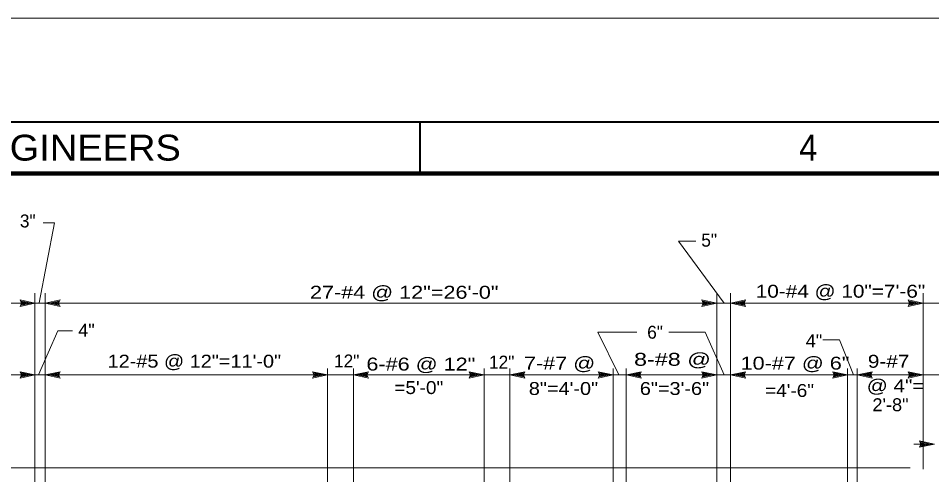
# Model space of a CAD drawing. Extents: x -22.3 to 19.7, y -11.8 to 18.2.
# Drawn here: x -17.19 to -8.36, y 13.75 to 18.16 of the extents above; entities that cross this region are included whole.
import ezdxf
from ezdxf.enums import TextEntityAlignment as Align

# ---------------------------------------------------------------- set-up
doc = ezdxf.new("R2010")
doc.units = 0
doc.header["$LTSCALE"] = 0.05
doc.layers.add('1', color=7, linetype='Continuous', lineweight=13)

msp = doc.modelspace()

# ---------------------------------------------------------------- linework, layer by layer
at = {"layer": '1', "lineweight": 40}
msp.add_line((-13.30942, 17.16031), (-13.30942, 16.66031), dxfattribs=at)
at = {"layer": '1'}
for p, q in [((-10.36542, 15.40731), (-10.80942, 16.00631)), ((-10.80942, 16.00631), (-10.63942, 16.00631)), ((-17.03142, 9.51631), (-17.03142, 15.50531)), ((-16.93242, 9.51631), (-16.93242, 15.50531)), ((-10.43842, 12.78231), (-10.43842, 15.50531)), ((-10.30342, 12.84831), (-10.30342, 15.50531)), ((-8.44242, 13.80331), (-8.44242, 15.50531)), ((-17.03142, 15.40731), (-17.17542, 15.43831)), ((-17.03142, 15.40731), (-17.17542, 15.37631)), ((-17.06842, 15.40731), (-17.16242, 15.42731)), ((-17.15342, 15.40731), (-17.16242, 15.42731)), ((-17.06842, 15.40731), (-17.16242, 15.38731)), ((-17.16242, 15.38731), (-17.15342, 15.40731)), ((-17.10442, 15.40731), (-17.14942, 15.41631)), ((-17.14542, 15.40731), (-17.14942, 15.41631)), ((-17.10442, 15.40731), (-17.14942, 15.39731)), ((-17.14942, 15.39731), (-17.14542, 15.40731)), ((-16.93242, 15.40731), (-16.78842, 15.43831)), ((-16.93242, 15.40731), (-16.78842, 15.37631)), ((-16.89542, 15.40731), (-16.80142, 15.42731)), ((-16.89542, 15.40731), (-16.80142, 15.38731)), ((-16.85942, 15.40731), (-16.81442, 15.41731)), ((-16.85942, 15.40731), (-16.81442, 15.39831)), ((-16.81442, 15.41731), (-16.81842, 15.40731)), ((-16.81842, 15.40731), (-16.81442, 15.39831)), ((-16.80142, 15.42731), (-16.81042, 15.40731)), ((-16.81042, 15.40731), (-16.80142, 15.38731)), ((-10.43842, 15.40731), (-10.58242, 15.43831)), ((-10.43842, 15.40731), (-10.58242, 15.37631)), ((-10.47542, 15.40731), (-10.56942, 15.42731)), ((-10.56042, 15.40731), (-10.56942, 15.42731)), ((-10.47542, 15.40731), (-10.56942, 15.38731)), ((-10.56942, 15.38731), (-10.56042, 15.40731)), ((-10.51142, 15.40731), (-10.55642, 15.41631)), ((-10.55242, 15.40731), (-10.55642, 15.41631)), ((-10.51142, 15.40731), (-10.55642, 15.39731)), ((-10.55642, 15.39731), (-10.55242, 15.40731)), ((-10.30242, 15.40731), (-10.15842, 15.43831)), ((-10.30242, 15.40731), (-10.15842, 15.37631)), ((-10.26542, 15.40731), (-10.17142, 15.42731)), ((-10.26542, 15.40731), (-10.17142, 15.38731)), ((-10.22942, 15.40731), (-10.18442, 15.41731)), ((-10.22942, 15.40731), (-10.18442, 15.39831)), ((-10.18442, 15.41731), (-10.18842, 15.40731)), ((-10.18842, 15.40731), (-10.18442, 15.39831)), ((-10.17142, 15.42731), (-10.18042, 15.40731)), ((-10.18042, 15.40731), (-10.17142, 15.38731)), ((-8.44242, 15.40731), (-8.58642, 15.43831)), ((-8.44242, 15.40731), (-8.58642, 15.37631)), ((-8.47942, 15.40731), (-8.57342, 15.42731)), ((-8.56442, 15.40731), (-8.57342, 15.42731)), ((-8.47942, 15.40731), (-8.57342, 15.38731)), ((-8.57342, 15.38731), (-8.56442, 15.40731)), ((-8.51542, 15.40731), (-8.56042, 15.41631)), ((-8.55642, 15.40731), (-8.56042, 15.41631)), ((-8.51542, 15.40731), (-8.56042, 15.39731)), ((-8.56042, 15.39731), (-8.55642, 15.40731)), ((-16.81042, 15.13931), (-16.99742, 14.71431)), ((-16.81042, 15.13931), (-16.66942, 15.13931)), ((-11.38342, 14.71431), (-11.58742, 15.12631)), ((-11.58742, 15.12631), (-11.21142, 15.12631)), ((-10.90242, 15.12631), (-10.55042, 15.12631)), ((-10.55042, 15.12631), (-10.36542, 14.71431)), ((-14.20242, 10.90131), (-14.20242, 14.77631)), ((-13.95142, 11.04731), (-13.95142, 14.77631)), ((-12.68842, 11.68931), (-12.68842, 14.77631)), ((-12.43842, 11.79131), (-12.43842, 14.77631)), ((-11.43942, 12.29431), (-11.43942, 14.77631)), ((-11.31242, 10.81431), (-11.31242, 14.77631)), ((-9.17242, 13.43131), (-9.17242, 14.77631)), ((-9.08142, 10.74131), (-9.08142, 14.77631)), ((-17.03142, 14.71431), (-17.17542, 14.74531)), ((-17.03142, 14.71431), (-17.17542, 14.68331)), ((-17.06842, 14.71431), (-17.16242, 14.73431)), ((-17.15342, 14.71431), (-17.16242, 14.73431)), ((-17.06842, 14.71431), (-17.16242, 14.69431)), ((-17.16242, 14.69431), (-17.15342, 14.71431)), ((-17.10442, 14.71431), (-17.14942, 14.72331)), ((-17.14542, 14.71431), (-17.14942, 14.72331)), ((-17.10442, 14.71431), (-17.14942, 14.70431)), ((-17.14942, 14.70431), (-17.14542, 14.71431)), ((-16.93242, 14.71431), (-16.78842, 14.74531)), ((-16.93242, 14.71431), (-16.78842, 14.68331)), ((-16.89542, 14.71431), (-16.80142, 14.73431)), ((-16.89542, 14.71431), (-16.80142, 14.69431)), ((-16.85942, 14.71431), (-16.81442, 14.72431)), ((-16.85942, 14.71431), (-16.81442, 14.70531)), ((-16.81442, 14.72431), (-16.81842, 14.71431)), ((-16.81842, 14.71431), (-16.81442, 14.70531)), ((-16.80142, 14.73431), (-16.81042, 14.71431)), ((-16.81042, 14.71431), (-16.80142, 14.69431)), ((-14.20242, 14.71431), (-14.34642, 14.74531)), ((-14.20242, 14.71431), (-14.34642, 14.68331)), ((-14.23942, 14.71431), (-14.33342, 14.73431)), ((-14.32442, 14.71431), (-14.33342, 14.73431)), ((-14.23942, 14.71431), (-14.33342, 14.69431)), ((-14.33342, 14.69431), (-14.32442, 14.71431)), ((-14.27542, 14.71431), (-14.32042, 14.72331)), ((-14.31642, 14.71431), (-14.32042, 14.72331)), ((-14.27542, 14.71431), (-14.32042, 14.70431)), ((-14.32042, 14.70431), (-14.31642, 14.71431)), ((-13.95142, 14.71431), (-13.80742, 14.74531)), ((-13.95142, 14.71431), (-13.80742, 14.68331)), ((-13.91442, 14.71431), (-13.82042, 14.73431)), ((-13.91442, 14.71431), (-13.82042, 14.69431)), ((-13.87842, 14.71431), (-13.83342, 14.72431)), ((-13.87842, 14.71431), (-13.83342, 14.70531)), ((-13.83342, 14.72431), (-13.83742, 14.71431)), ((-13.83742, 14.71431), (-13.83342, 14.70531)), ((-13.82042, 14.73431), (-13.82942, 14.71431)), ((-13.82942, 14.71431), (-13.82042, 14.69431)), ((-12.68842, 14.71431), (-12.83242, 14.74531)), ((-12.68842, 14.71431), (-12.83242, 14.68331)), ((-12.72542, 14.71431), (-12.81942, 14.73431)), ((-12.81042, 14.71431), (-12.81942, 14.73431)), ((-12.72542, 14.71431), (-12.81942, 14.69431)), ((-12.81942, 14.69431), (-12.81042, 14.71431)), ((-12.76142, 14.71431), (-12.80642, 14.72331)), ((-12.80242, 14.71431), (-12.80642, 14.72331)), ((-12.76142, 14.71431), (-12.80642, 14.70431)), ((-12.80642, 14.70431), (-12.80242, 14.71431)), ((-12.43842, 14.71431), (-12.29442, 14.74531)), ((-12.43842, 14.71431), (-12.29442, 14.68331)), ((-12.40142, 14.71431), (-12.30742, 14.73431)), ((-12.40142, 14.71431), (-12.30742, 14.69431)), ((-12.36542, 14.71431), (-12.32042, 14.72431)), ((-12.36542, 14.71431), (-12.32042, 14.70531)), ((-12.32042, 14.72431), (-12.32442, 14.71431)), ((-12.32442, 14.71431), (-12.32042, 14.70531)), ((-12.30742, 14.73431), (-12.31642, 14.71431)), ((-12.31642, 14.71431), (-12.30742, 14.69431)), ((-11.43942, 14.71431), (-11.58342, 14.74531)), ((-11.43942, 14.71431), (-11.58342, 14.68331)), ((-11.47642, 14.71431), (-11.57042, 14.73431)), ((-11.56142, 14.71431), (-11.57042, 14.73431)), ((-11.47642, 14.71431), (-11.57042, 14.69431)), ((-11.57042, 14.69431), (-11.56142, 14.71431)), ((-11.51242, 14.71431), (-11.55742, 14.72331)), ((-11.55342, 14.71431), (-11.55742, 14.72331)), ((-11.51242, 14.71431), (-11.55742, 14.70431)), ((-11.55742, 14.70431), (-11.55342, 14.71431)), ((-11.31142, 14.71431), (-11.16742, 14.74531)), ((-11.31142, 14.71431), (-11.16742, 14.68331)), ((-11.27442, 14.71431), (-11.18042, 14.73431)), ((-11.27442, 14.71431), (-11.18042, 14.69431)), ((-11.23842, 14.71431), (-11.19342, 14.72431)), ((-11.23842, 14.71431), (-11.19342, 14.70531)), ((-11.19342, 14.72431), (-11.19742, 14.71431)), ((-11.19742, 14.71431), (-11.19342, 14.70531)), ((-11.18042, 14.73431), (-11.18942, 14.71431)), ((-11.18942, 14.71431), (-11.18042, 14.69431)), ((-10.43842, 14.71431), (-10.58242, 14.74531)), ((-10.43842, 14.71431), (-10.58242, 14.68331)), ((-10.47542, 14.71431), (-10.56942, 14.73431)), ((-10.56042, 14.71431), (-10.56942, 14.73431)), ((-10.47542, 14.71431), (-10.56942, 14.69431)), ((-10.56942, 14.69431), (-10.56042, 14.71431)), ((-10.51142, 14.71431), (-10.55642, 14.72331)), ((-10.55242, 14.71431), (-10.55642, 14.72331)), ((-10.51142, 14.71431), (-10.55642, 14.70431)), ((-10.55642, 14.70431), (-10.55242, 14.71431)), ((-10.30342, 14.71431), (-10.15942, 14.74531)), ((-10.30342, 14.71431), (-10.15942, 14.68331)), ((-10.26642, 14.71431), (-10.17242, 14.73431)), ((-10.26642, 14.71431), (-10.17242, 14.69431)), ((-10.23042, 14.71431), (-10.18542, 14.72431)), ((-10.23042, 14.71431), (-10.18542, 14.70531)), ((-10.18542, 14.72431), (-10.18942, 14.71431)), ((-10.18942, 14.71431), (-10.18542, 14.70531)), ((-10.17242, 14.73431), (-10.18142, 14.71431)), ((-10.18142, 14.71431), (-10.17242, 14.69431)), ((-9.17242, 14.71431), (-9.31642, 14.74531)), ((-9.17242, 14.71431), (-9.31642, 14.68331)), ((-9.20942, 14.71431), (-9.30342, 14.73431)), ((-9.29442, 14.71431), (-9.30342, 14.73431)), ((-9.20942, 14.71431), (-9.30342, 14.69431)), ((-9.30342, 14.69431), (-9.29442, 14.71431)), ((-9.24542, 14.71431), (-9.29042, 14.72331)), ((-9.28642, 14.71431), (-9.29042, 14.72331)), ((-9.24542, 14.71431), (-9.29042, 14.70431)), ((-9.29042, 14.70431), (-9.28642, 14.71431)), ((-9.07942, 14.71431), (-8.93542, 14.74531)), ((-9.07942, 14.71431), (-8.93542, 14.68331)), ((-9.04242, 14.71431), (-8.94842, 14.73431)), ((-9.04242, 14.71431), (-8.94842, 14.69431)), ((-9.00642, 14.71431), (-8.96142, 14.72431)), ((-9.00642, 14.71431), (-8.96142, 14.70531)), ((-8.96142, 14.72431), (-8.96542, 14.71431)), ((-8.96542, 14.71431), (-8.96142, 14.70531)), ((-8.94842, 14.73431), (-8.95742, 14.71431)), ((-8.95742, 14.71431), (-8.94842, 14.69431)), ((-8.44242, 14.71431), (-8.58642, 14.74531)), ((-8.44242, 14.71431), (-8.58642, 14.68331)), ((-8.47942, 14.71431), (-8.57342, 14.73431)), ((-8.56442, 14.71431), (-8.57342, 14.73431)), ((-8.47942, 14.71431), (-8.57342, 14.69431)), ((-8.57342, 14.69431), (-8.56442, 14.71431)), ((-8.51542, 14.71431), (-8.56042, 14.72331)), ((-8.55642, 14.71431), (-8.56042, 14.72331)), ((-8.51542, 14.71431), (-8.56042, 14.70431)), ((-8.56042, 14.70431), (-8.55642, 14.71431)), ((-8.53242, 14.04631), (-8.33342, 14.04631)), ((-8.33342, 14.04631), (-8.47742, 14.07731)), ((-8.33342, 14.04631), (-8.47742, 14.01531)), ((-8.37042, 14.04631), (-8.46442, 14.06631)), ((-8.45542, 14.04631), (-8.46442, 14.06631)), ((-8.37042, 14.04631), (-8.46442, 14.02631)), ((-8.46442, 14.02631), (-8.45542, 14.04631)), ((-8.40642, 14.04631), (-8.45142, 14.05531)), ((-8.44742, 14.04631), (-8.45142, 14.05531)), ((-8.40642, 14.04631), (-8.45142, 14.03631)), ((-8.45142, 14.03631), (-8.44742, 14.04631)), ((-8.56742, 13.81631), (-19.00142, 13.81631))]:
    msp.add_line(p, q, dxfattribs=at)
for points in [[(-22.30942, 18.16031), (19.69058, 18.16031), (19.69058, -11.83969)], [(-16.95342, 16.18331), (-16.84342, 16.18331), (-16.99042, 15.41031)], [(-18.06742, 15.40731), (-17.03142, 15.40731), (-16.93242, 15.40731), (-10.43842, 15.40731), (-10.30242, 15.40731), (-8.44242, 15.40731), (-8.32942, 15.40731), (-7.44542, 15.40731)], [(-17.17542, 15.37631), (-17.16142, 15.40731), (-17.17542, 15.43831)], [(-16.78842, 15.43831), (-16.80242, 15.40731), (-16.78842, 15.37631)], [(-10.58242, 15.37631), (-10.56842, 15.40731), (-10.58242, 15.43831)], [(-10.15842, 15.43831), (-10.17242, 15.40731), (-10.15842, 15.37631)], [(-8.58642, 15.37631), (-8.57242, 15.40731), (-8.58642, 15.43831)], [(-9.11542, 14.71431), (-9.25242, 15.05231), (-9.41242, 15.05231)], [(-18.10442, 14.71431), (-17.03142, 14.71431), (-16.93242, 14.71431), (-14.20242, 14.71431), (-13.95142, 14.71431), (-12.68842, 14.71431), (-12.43842, 14.71431), (-11.43942, 14.71431), (-11.31142, 14.71431), (-10.43842, 14.71431), (-10.30342, 14.71431), (-9.17242, 14.71431), (-9.07942, 14.71431), (-8.44242, 14.71431), (-8.33342, 14.71431), (-7.78542, 14.71431)], [(-17.17542, 14.68331), (-17.16142, 14.71431), (-17.17542, 14.74531)], [(-16.78842, 14.74531), (-16.80242, 14.71431), (-16.78842, 14.68331)], [(-14.34642, 14.68331), (-14.33242, 14.71431), (-14.34642, 14.74531)], [(-13.80742, 14.74531), (-13.82142, 14.71431), (-13.80742, 14.68331)], [(-12.83242, 14.68331), (-12.81842, 14.71431), (-12.83242, 14.74531)], [(-12.29442, 14.74531), (-12.30842, 14.71431), (-12.29442, 14.68331)], [(-11.58342, 14.68331), (-11.56942, 14.71431), (-11.58342, 14.74531)], [(-11.16742, 14.74531), (-11.18142, 14.71431), (-11.16742, 14.68331)], [(-10.58242, 14.68331), (-10.56842, 14.71431), (-10.58242, 14.74531)], [(-10.15942, 14.74531), (-10.17342, 14.71431), (-10.15942, 14.68331)], [(-9.31642, 14.68331), (-9.30242, 14.71431), (-9.31642, 14.74531)], [(-8.93542, 14.74531), (-8.94942, 14.71431), (-8.93542, 14.68331)], [(-8.58642, 14.68331), (-8.57242, 14.71431), (-8.58642, 14.74531)], [(-8.47742, 14.01531), (-8.46342, 14.04631), (-8.47742, 14.07731)]]:
    msp.add_lwpolyline(points, dxfattribs=at)
at = {"layer": '1', "lineweight": 40}
msp.add_lwpolyline([(-21.30942, -10.83969), (-21.30942, 17.16031), (18.69058, 17.16031), (18.69058, -10.83969)], close=True, dxfattribs=at)
at = {"layer": '1', "lineweight": 90}
msp.add_lwpolyline([(-19.80942, 16.66031), (18.19058, 16.66031), (18.19058, -10.33969), (-19.80942, -10.33969)], close=True, dxfattribs=at)

# ---------------------------------------------------------------- texts
at = {"layer": '1'}
for s, height, width, p in [('CORPS OF ENGINEERS', 0.25, 1.1, (-19.80942, 16.78531)), ('4"', 0.125, 1.05, (-16.61342, 15.08331))]:
    msp.add_text(s, height=height, dxfattribs=dict(at, width=width)).set_placement(p)
for s, height, width, p in [('4', 0.25, 0.95, (-9.55292, 16.78531)), ('27-#4 @ 12"=26\'-0"', 0.125, 1.25, (-13.46042, 15.45031)), ('10-#4 @ 10"=7\'-6"', 0.125, 1.2, (-9.24142, 15.46031)), ('8-#8 @ ', 0.125, 1.35, (-10.83492, 14.80231)), ('12-#5 @ 12"=11\'-0"', 0.125, 1.15, (-15.48992, 14.78431)), ('6-#6 @ 12"', 0.125, 1.25, (-13.29942, 14.75631)), ('7-#7 @', 0.125, 1.25, (-11.95792, 14.76531)), ('10-#7 @ 6"', 0.125, 1.25, (-9.68092, 14.76531)), ('9-#7', 0.125, 1.2, (-8.77592, 14.78331)), ('@ 4"=', 0.125, 1.2, (-8.70792, 14.54731)), ('=5\'-0"', 0.125, 1.1, (-13.31942, 14.52931)), ('8"=4\'-0"', 0.125, 1.15, (-11.92042, 14.52031)), ('6"=3\'-6"', 0.125, 1.15, (-10.84692, 14.52031)), ('=4\'-6"', 0.125, 1.1, (-9.73392, 14.50131)), ('2\'-8"', 0.125, 1.05, (-8.75792, 14.36331))]:
    msp.add_text(s, height=height, dxfattribs=dict(at, width=width)).set_placement(p, align=Align.CENTER)
for s, p in [('3"', (-17.17742, 16.13931)), ('5"', (-10.58742, 15.95331)), ('12"', (-14.13942, 14.78631)), ('12"', (-12.64042, 14.77531))]:
    msp.add_text(s, height=0.125, dxfattribs=at).set_placement(p)
msp.add_text('6"', height=0.125, dxfattribs=at).set_placement((-11.03442, 15.06431), align=Align.CENTER)
at = {"layer": '1', "width": 1.05}
msp.add_text('4"', height=0.125, dxfattribs=at).set_placement((-9.41742, 14.98131), align=Align.RIGHT)

doc.saveas('drawing.dxf')
